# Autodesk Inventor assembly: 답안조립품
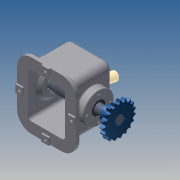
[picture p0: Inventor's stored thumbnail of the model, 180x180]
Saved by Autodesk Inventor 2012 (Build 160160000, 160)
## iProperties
Created: 2014-11
Part Number: 답안조립품
Document SubType Name: Assembly
Designer: Owner
Author: Owner
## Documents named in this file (13)
- C:\Documents and Settings\Owner\바탕 화면\441122V1004\답안조립품.iam
- C:\Documents and Settings\Owner\바탕 화면\441122V1004\본체.ipt
- C:\Documents and Settings\Owner\바탕 화면\441122V1004\5-체인 스프로킷.ipt
- C:\Documents and Settings\Owner\바탕 화면\441122V1004\뒤커버.ipt
- C:\Documents and Settings\Owner\바탕 화면\441122V1004\멈춤나사 M5x0.5.ipt
- C:\Documents and Settings\Owner\바탕 화면\441122V1004\베어링 6205.ipt
- C:\Documents and Settings\Owner\바탕 화면\441122V1004\부시.ipt
- C:\Documents and Settings\Owner\바탕 화면\441122V1004\M4x0.5.ipt
- C:\Documents and Settings\Owner\바탕 화면\441122V1004\슬라이드.ipt
- C:\Documents and Settings\Owner\바탕 화면\441122V1004\앞커버.ipt
- C:\Documents and Settings\Owner\바탕 화면\441122V1004\오일실.ipt
- C:\Documents and Settings\Owner\바탕 화면\441122V1004\키 8x8.ipt
- C:\Documents and Settings\Owner\바탕 화면\441122V1004\편심축.ipt
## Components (9 placed, 2 different names)
1. 5-체인 스프로킷:1 — 플러쉬:3
2. M4x0.5:1 — 각도:3
3. M4x0.5:2 — 각도:2
4. M4x0.5:3 — 각도:6
5. M4x0.5:4 — 각도:7
6. M4x0.5:5 — 각도:5
7. M4x0.5:6 — 각도:8
8. M4x0.5:7 — 각도:4
9. M4x0.5:8 — 각도:1
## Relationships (9: Angle 8, Flush 1)
- 플러쉬:3 [Flush]: 5-체인 스프로킷:1
- 각도:1 [Angle]: M4x0.5:8
- 각도:2 [Angle]: M4x0.5:2
- 각도:3 [Angle]: M4x0.5:1
- 각도:4 [Angle]: M4x0.5:7
- 각도:5 [Angle]: M4x0.5:5
- 각도:6 [Angle]: M4x0.5:3
- 각도:7 [Angle]: M4x0.5:4
- 각도:8 [Angle]: M4x0.5:6
